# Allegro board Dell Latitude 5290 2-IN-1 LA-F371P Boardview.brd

Outline 162.9 x 178.5 mm; copper layers: TOP, IN1, GND1, IN2, GND2, VCC, IN3, GND3, IN4, BOTTOM. Coordinates in mm from the lower left corner of the outline.

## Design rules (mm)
net group ALS_I2C1_SDA: nets ALS_I2C1_SCL ALS_I2C1_SDA
net group BASE_SMBCLK: nets BASE_SMBCLK BASE_SMBDAT
net group DIFFPAIR25: nets SATA_PRX_SSDTX_N8 SATA_PRX_SSDTX_P8
net group DIFFPAIR26: nets SATA_PTX_SSDRX_N8 SATA_PTX_SSDRX_P8
net group DIFFPAIR27: nets SATA_PTX_SSDRX_N8_C SATA_PTX_SSDRX_P8_C
net group I2C1_CLK_PD1: nets I2C1_CLK_PD1 I2C1_DAT_PD1
net group I2C1_SCK_TS: nets I2C1_SCK_TS I2C1_SDA_TS
net group PD1_AUX_: nets PD1_AUX_N PD1_AUX_P
net group PD2_AUX_: nets PD2_AUX_N PD2_AUX_P
net group REM_DIODE1_P: nets REM_DIODE1_N REM_DIODE1_P
net group REM_DIODE2_P: nets REM_DIODE2_N REM_DIODE2_P
net group REM_DIODE3_P: nets REM_DIODE3_N REM_DIODE3_P
net group SD_LN0_P: nets SD_LN0_M SD_LN0_P
net group SD_LN1_P: nets SD_LN1_M SD_LN1_P
net group SD_RCLK_P: nets SD_RCLK_M SD_RCLK_P
net group SD_RCLK_P_L: nets SD_RCLK_M_L SD_RCLK_P_L
net group USB3RP1_C: nets USB3RN1_C USB3RP1_C
net group USB3TP1_C: nets USB3TN1_C USB3TP1_C
net group 10: nets CL_RST# PCH_RSMRST# PLT_RST# RTC_RST# UIM_CLK UIM_DATA UIM_DET UIM_DET# UIM_RESET WLAN_RST# WLAN_RST#_Q WWAN_RST#
net group 10_20: nets SPK_-OUT-L+ SPK_-OUT-L- SPK_-OUT-R+ SPK_-OUT-R- SPK_L+ SPK_L- SPK_R+ SPK_R-
net group 12: nets CLK1_PCIE_WLAN CLK1_PCIE_WLAN# CLK1_PCIE_WLAN#_R CLK1_PCIE_WLAN_R CLK2_PCIE_WWAN CLK2_PCIE_WWAN# CLK2_PCIE_WWAN#_R CLK2_PCIE_WWAN_R CLK_ITPXDP_N CLK_ITPXDP_N_R CLK_ITPXDP_P CLK_ITPXDP_P_R CLK_PCIE_MMI CLK_PCIE_MMI# CLK_PCIE_MMI#_R CLK_PCIE_MMI_R CLK_PCIE_SSD CLK_PCIE_SSD# CLK_PCIE_SSD#_R CLK_PCIE_SSD_R PCIE_PRX_CARDTX_N9_C PCIE_PRX_CARDTX_P9_C PCIE_PTX_CARDRX_N9_C PCIE_PTX_CARDRX_P9_C UFCAM_CSI2_CLKN0 UFCAM_CSI2_CLKN0_L UFCAM_CSI2_CLKP0 UFCAM_CSI2_CLKP0_L UFCAM_CSI2_DN0 UFCAM_CSI2_DN0_L UFCAM_CSI2_DN1 UFCAM_CSI2_DN1_L UFCAM_CSI2_DP0 UFCAM_CSI2_DP0_L UFCAM_CSI2_DP1 UFCAM_CSI2_DP1_L USB3RN1 USB3RN2 USB3RN3_CONN USB3RN4 USB3RN4_C USB3RP1 USB3RP2 USB3RP3_CONN USB3RP4 USB3RP4_C USB3TN3 USB3TN3_CONN USB3TN4 USB3TN4_C USB3TP3 USB3TP3_CONN USB3TP4 USB3TP4_C USB20_N1 USB20_N1_R USB20_N3_R USB20_N4 USB20_N4_CONN USB20_N5_CONN USB20_N10 USB20_P1 USB20_P1_R USB20_P3_R USB20_P4 USB20_P4_CONN USB20_P5_CONN USB20_P10 USBC1_BN2_L USBC1_BOT_DN2 USBC1_BOT_DP2 USBC1_BP2_L USBC1_TN1_L USBC1_TOP_DN1 USBC1_TOP_DP1 USBC1_TP1_L USBC2_BN2_L USBC2_BOT_DN2 USBC2_BOT_DP2 USBC2_BP2_L USBC2_TN1_L USBC2_TOP_DN1 USBC2_TOP_DP1 USBC2_TP1_L WFCAM_CSI2_CLKN1 WFCAM_CSI2_CLKN1_L WFCAM_CSI2_CLKP1 WFCAM_CSI2_CLKP1_L WFCAM_CSI2_DN4 WFCAM_CSI2_DN4_L WFCAM_CSI2_DN5 WFCAM_CSI2_DN5_L WFCAM_CSI2_DN6 WFCAM_CSI2_DN6_L WFCAM_CSI2_DN7 WFCAM_CSI2_DN7_L WFCAM_CSI2_DP4 WFCAM_CSI2_DP4_L WFCAM_CSI2_DP5 WFCAM_CSI2_DP5_L WFCAM_CSI2_DP6 WFCAM_CSI2_DP6_L WFCAM_CSI2_DP7 WFCAM_CSI2_DP7_L
net group 15: nets CL_CLK CL_DATA DDR_XDP_SMBCLK DDR_XDP_SMBDAT HDA_BLK HDA_BLK_L HDA_BLK_R I2C2_CLK_PD1 I2C2_DAT_PD1 ISH_I2C0_SDA JTAG_CLK MUX2_CSCL MUX2_CSDA PCH_JTAG_TCLK PCH_SPI_CLK_TPM PCI_CLK_LPC0 PCI_CLK_LPC1 SKYCAM_I2C_CLK SKYCAM_I2C_DATA SML1_SMBCLK SML1_SMBDAT SPI_CLK_VROM1 SRTCRST# SUSCLK SUSCLK_L SYS_RESET# SYS_RESET#_R UF_HCLK UF_HCLK_R UF_I2C_CLK UF_I2C_DATA UF_SENSOR_RST# UF_SENSOR_RST#_R USH_RST# USH_RST#_L VSS_GT_SENSE WF_HCLK WF_HCLK_R WF_I2C_CLK WF_I2C_DATA WF_SENSOR_RST# WF_SENSOR_RST#_R XDP_DBRESET#
net group 20: nets +V_DDR_REF_CA +V_DDR_REFA_R +V_DDR_REFB_R
net group DDR0_7.5_12_25: nets DDR_A_D16 DDR_A_D17 DDR_A_D18 DDR_A_D19 DDR_A_D20 DDR_A_D21 DDR_A_D22 DDR_A_D23 DDR_A_D32 DDR_A_D33 DDR_A_D34 DDR_A_D35 DDR_A_D36 DDR_A_D37 DDR_A_D38 DDR_A_D39 DDR_A_D48 DDR_A_D49 DDR_A_D50 DDR_A_D51 DDR_A_D52 DDR_A_D53 DDR_A_D54 DDR_A_D55 DDR_B_D0 DDR_B_D1 DDR_B_D2 DDR_B_D3 DDR_B_D4 DDR_B_D5 DDR_B_D6 DDR_B_D7 DDR_B_D16 DDR_B_D17 DDR_B_D18 DDR_B_D19 DDR_B_D20 DDR_B_D21 DDR_B_D22 DDR_B_D23 DDR_B_D32 DDR_B_D33 DDR_B_D34 DDR_B_D35 DDR_B_D36 DDR_B_D37 DDR_B_D38 DDR_B_D39 DDR_B_D48 DDR_B_D49 DDR_B_D50 DDR_B_D51 DDR_B_D52 DDR_B_D53 DDR_B_D54 DDR_B_D55 DDR_B_D56 DDR_B_D57 DDR_B_D58 DDR_B_D59 DDR_B_D60 DDR_B_D61 DDR_B_D62 DDR_B_D63
net group DDR1_7.5_12_25: nets DDR_A_D0 DDR_A_D1 DDR_A_D2 DDR_A_D3 DDR_A_D4 DDR_A_D5 DDR_A_D6 DDR_A_D7 DDR_A_D8 DDR_A_D9 DDR_A_D10 DDR_A_D11 DDR_A_D12 DDR_A_D13 DDR_A_D14 DDR_A_D15 DDR_A_D24 DDR_A_D25 DDR_A_D26 DDR_A_D27 DDR_A_D28 DDR_A_D29 DDR_A_D30 DDR_A_D31 DDR_A_D40 DDR_A_D41 DDR_A_D42 DDR_A_D43 DDR_A_D44 DDR_A_D45 DDR_A_D46 DDR_A_D47 DDR_A_D56 DDR_A_D57 DDR_A_D58 DDR_A_D59 DDR_A_D60 DDR_A_D61 DDR_A_D62 DDR_A_D63 DDR_B_D8 DDR_B_D9 DDR_B_D10 DDR_B_D11 DDR_B_D12 DDR_B_D13 DDR_B_D14 DDR_B_D15 DDR_B_D24 DDR_B_D25 DDR_B_D26 DDR_B_D27 DDR_B_D28 DDR_B_D29 DDR_B_D30 DDR_B_D31 DDR_B_D40 DDR_B_D41 DDR_B_D42 DDR_B_D43 DDR_B_D44 DDR_B_D45 DDR_B_D46 DDR_B_D47
net group DDRACMD_7.5_12: nets DDR_A_CA1_0 DDR_A_CA1_1 DDR_A_CA1_2 DDR_A_CA1_3 DDR_A_CA1_4 DDR_A_CA1_5 DDR_A_CA1_6 DDR_A_CA1_7 DDR_A_CA1_8 DDR_A_CA1_9 DDR_A_CA2_0 DDR_A_CA2_1 DDR_A_CA2_2 DDR_A_CA2_3 DDR_A_CA2_4 DDR_A_CA2_5 DDR_A_CA2_6 DDR_A_CA2_7 DDR_A_CA2_8 DDR_A_CA2_9
net group DDRBCMD_7.5_12: nets DDR_B_CA1_0 DDR_B_CA1_1 DDR_B_CA1_2 DDR_B_CA1_3 DDR_B_CA1_4 DDR_B_CA1_5 DDR_B_CA1_6 DDR_B_CA1_7 DDR_B_CA1_8 DDR_B_CA1_9 DDR_B_CA2_0 DDR_B_CA2_1 DDR_B_CA2_2 DDR_B_CA2_3 DDR_B_CA2_4 DDR_B_CA2_5 DDR_B_CA2_6 DDR_B_CA2_7 DDR_B_CA2_8 DDR_B_CA2_9
net group DDRCKE_7.5_12: nets DDR_A_CKE0 DDR_A_CKE1 DDR_A_CKE2 DDR_A_CKE3 DDR_B_CKE0 DDR_B_CKE1 DDR_B_CKE2 DDR_B_CKE3
net group DDRCLK_12_25: nets DDR_A_CLK0 DDR_A_CLK1 DDR_A_CLK#0 DDR_A_CLK#1 DDR_B_CLK0 DDR_B_CLK1 DDR_B_CLK#0 DDR_B_CLK#1
net group DDRCTL_7.5_12: nets DDR_A_CS#0 DDR_A_CS#1 DDR_A_ODT0 DDR_B_CS#0 DDR_B_CS#1 DDR_B_ODT0
net group DDRDQS_12_25: nets DDR_A_DQS0 DDR_A_DQS1 DDR_A_DQS2 DDR_A_DQS3 DDR_A_DQS4 DDR_A_DQS5 DDR_A_DQS6 DDR_A_DQS7 DDR_A_DQS#0 DDR_A_DQS#1 DDR_A_DQS#2 DDR_A_DQS#3 DDR_A_DQS#4 DDR_A_DQS#5 DDR_A_DQS#6 DDR_A_DQS#7 DDR_B_DQS0 DDR_B_DQS1 DDR_B_DQS2 DDR_B_DQS3 DDR_B_DQS4 DDR_B_DQS5 DDR_B_DQS6 DDR_B_DQS7 DDR_B_DQS#0 DDR_B_DQS#1 DDR_B_DQS#2 DDR_B_DQS#3 DDR_B_DQS#4 DDR_B_DQS#5 DDR_B_DQS#6 DDR_B_DQS#7
net group DP: nets DDI1_P2_TXN2_C DDI1_P2_TXP2 DDI1_P2_TXP2_C PD1_SBU1 PD1_SBU2 PD2_SBU1 PD2_SBU2 USBC1_SBU1 USBC2_SBU1 USBC2_SBU2 UV1_SBU1 UV1_SBU2 UV2_SBU1 UV2_SBU2
net group DP_12_15: nets DDI1_P2_TXN0 DDI1_P2_TXN0_C DDI1_P2_TXN1 DDI1_P2_TXN1_C DDI1_P2_TXN2 DDI1_P2_TXN3 DDI1_P2_TXN3_C DDI1_P2_TXP0 DDI1_P2_TXP0_C DDI1_P2_TXP1 DDI1_P2_TXP1_C DDI1_P2_TXP3 DDI1_P2_TXP3_C DDI2_P1_AUXN_C DDI2_P1_AUXP_C DDI2_P1_TXN0_C DDI2_P1_TXN1_C DDI2_P1_TXN2_C DDI2_P1_TXN3_C DDI2_P1_TXP0_C DDI2_P1_TXP1_C DDI2_P1_TXP2_C DDI2_P1_TXP3_C PCH_DDI1_AUXN PCH_DDI1_AUXN_C PCH_DDI1_AUXP PCH_DDI1_AUXP_C PCH_DDI2_AUXN PCH_DDI2_AUXP PCH_DDI2_N0 PCH_DDI2_N1 PCH_DDI2_N2 PCH_DDI2_N3 PCH_DDI2_P0 PCH_DDI2_P1 PCH_DDI2_P2 PCH_DDI2_P3 USBC1_RX1N USBC1_RX1P USBC1_RX2N USBC1_RX2P USBC1_SBU2 USBC1_TX1N USBC1_TX1N_C USBC1_TX1P USBC1_TX1P_C USBC1_TX2N USBC1_TX2N_C USBC1_TX2P USBC1_TX2P_C USBC2_RX1N USBC2_RX1P USBC2_RX2N USBC2_RX2P USBC2_TX1N USBC2_TX1N_C USBC2_TX1P USBC2_TX1P_C USBC2_TX2N USBC2_TX2N_C USBC2_TX2P USBC2_TX2P_C
net group EC: nets JTAG_TDI JTAG_TDO JTAG_TMS
net group EDP_12_15: nets EDP_AUXN EDP_AUXN_CONN EDP_AUXN_R EDP_AUXP EDP_AUXP_CONN EDP_AUXP_R EDP_TXN_P0 EDP_TXN_P0_CONN EDP_TXN_P0_R EDP_TXN_P1 EDP_TXN_P1_CONN EDP_TXN_P1_R EDP_TXP_P0 EDP_TXP_P0_CONN EDP_TXP_P0_R EDP_TXP_P1 EDP_TXP_P1_CONN EDP_TXP_P1_R
net group HDA: nets HDA_SDI0 HDA_SDI0_L HDA_SDOUT HDA_SDOUT_R HDA_SYNC HDA_SYNC_R
net group I2C: nets CLK_SMB DAT_SMB GNSS_SCL ISH_I2C0_SCL PBAT_SMBCLK PBAT_SMBDAT
net group PCH_JTAG: nets TCLK_XDP TDI_XDP TDO_XDP TMS_XDP TRST#_XDP
net group PCIE: nets PCIE_PRX_CARDTX_N9 PCIE_PRX_CARDTX_P9 PCIE_PRX_SSDTX_N7 PCIE_PRX_SSDTX_P7 PCIE_PRX_WLANTX_N5 PCIE_PRX_WLANTX_P5 PCIE_PRX_WTX_UR_N12_SW PCIE_PRX_WTX_UR_N12_SW_CONN PCIE_PRX_WTX_UR_P12_SW PCIE_PRX_WTX_UR_P12_SW_CONN PCIE_PRX_WWANTX_N11 PCIE_PRX_WWANTX_N12 PCIE_PRX_WWANTX_P11 PCIE_PRX_WWANTX_P12 PCIE_PTX_CARDRX_N9 PCIE_PTX_CARDRX_P9 PCIE_PTX_SSDRX_N7 PCIE_PTX_SSDRX_N7_C PCIE_PTX_SSDRX_P7 PCIE_PTX_SSDRX_P7_C PCIE_PTX_WLANRX_N5 PCIE_PTX_WLANRX_N5_C PCIE_PTX_WLANRX_P5 PCIE_PTX_WLANRX_P5_C PCIE_PTX_WRX_UT_N12_SW PCIE_PTX_WRX_UT_N12_SW_CONN PCIE_PTX_WRX_UT_P12_SW PCIE_PTX_WRX_UT_P12_SW_CONN PCIE_PTX_WWANRX_N11 PCIE_PTX_WWANRX_N11_C PCIE_PTX_WWANRX_N12 PCIE_PTX_WWANRX_N12_C PCIE_PTX_WWANRX_P11 PCIE_PTX_WWANRX_P11_C PCIE_PTX_WWANRX_P12 PCIE_PTX_WWANRX_P12_C
net group SD: nets SD_CLK SD_CLK_L SD_CMD SD_CMD_L SD_D2 SD_D2_L SD_D3 SD_D3_L
net group SPI: nets PCH_SPI_CLK PCH_SPI_CS0# PCH_SPI_CS1# PCH_SPI_CS2# PCH_SPI_IO2 PCH_SPI_IO3 PCH_SPI_SI PCH_SPI_SI_TPM PCH_SPI_SO PCH_SPI_SO_TPM SPI_IO2_VROM1 SPI_IO3_VROM1 SPI_SI_VROM1 SPI_SO_VROM1 TPM_PIRQ#
net group SVID: nets H_CPU_SVIDALRT# VIDALERT_N VIDSCLK VIDSCLK_R VIDSOUT VIDSOUT_R
net group USB2.0: nets USB20_N2 USB20_N3 USB20_N5 USB20_N7 USB20_N7_R USB20_N9 USB20_N9_CONN USB20_N9_PS USB20_P2 USB20_P3 USB20_P5 USB20_P7 USB20_P7_R USB20_P9 USB20_P9_CONN USB20_P9_PS
net group USB3.0: nets USB3RN3 USB3RP3 USB3TN1 USB3TN2 USB3TN2_C USB3TN3_C USB3TP1 USB3TP2 USB3TP2_C USB3TP3_C
net group XDP: nets CFG0 CFG1 CFG2 CFG3 CFG4 CFG5 CFG6 CFG7 CFG8 CFG9 CFG10 CFG11 CFG12 CFG13 CFG14 CFG15 CFG16 CFG17 CFG18 CFG19 H_VCCST_PWRGD_XDP ITP_PMODE PCH_SPI_DO2_XDP PCH_SPI_DO_XDP SIO_PWRBTN# XDP_OBS0 XDP_OBS0_R XDP_OBS1 XDP_OBS1_R
nets with their own width: min track width 0.203; nets AK52 K52 N48802004 N48802006 N51064237 N51064241
nets with their own width: min track width 0.254; nets +1.0V_PRIM_COREP +1.2V_DDR +3VS_GYRO +VCC_SA +VCCCLK1 +VCCCLK2 +VCCCLK3 +VCCCLK4 +VCCCLK5 +VCCCLK6 EN_INVPWR_R HPOL_CONN HPOR_CONN HPOUT-L HPOUT-L_L HPOUT-R HPOUT-R_L MIC2-VREFO-L MIC2-VREFO-R N28846574 N34282781 N34283012 N41312056 N46285448 VCC_GT_SENSE VCCIO_SENSE VCCSENSE VSA_SEN+ VSA_SEN- VSSIO_SENSE VSSSENSE
nets with their own width: min track width 0.305; nets CFG_RCOMP CSI2_COMP EMMC_RCOMP PCIE_RCOMPN PCIE_RCOMPP SD_RCOMP SM_RCOMP0 SM_RCOMP1 SM_RCOMP2 USBCOMP
nets with their own width: min track width 0.381; nets +3V_LDO +VREFCA
nets with their own width: min track width 0.508; nets +0.6VSP +1.0V_AMPHYPLL +1.0V_APLL +1.0V_APLLEBB +1.0V_CLK +1.0V_DTS +1.0V_MPHYAON +1.0V_PRIM_CORE +1.0V_SRAM +1.0V_VCCST +1.0V_VCCSTG +1.0V_VCCSTG_R +1.0VA_XDP +1.0VAP +1.2V_DDRP +1.2V_MEM_CPUCLK +1.2V_MUX +1.2V_UF_DVDD +1.2V_WF_DVDD +1.5VS_AUDIO +1.8V_IO_OUT +1.8V_PGPP +1.8V_UF_VDD +1.8V_WF_DOVDD +1.8VA_LDO_PD1 +1.8VA_LDO_PD2 +1.8VAP +1.8VD_LDO_PD1 +1.8VD_LDO_PD2 +1.8VS +1.8VS_AUDIO +1.8VUP +2.8V_UF_AVDD +2.8V_VCM_OUT +2.8V_WF_AVDD +3.3V_LDO_PD1 +3.3V_LDO_PD2 +3.3V_PGPP +3.3V_SPI +3.3V_TBAT_LDO +3.3V_VOUT_PD1 +3.3V_VOUT_PD2 +3V_FAN +3V_LDOP +3V_PRIM +3V_RF +3V_SKYCAM +3VALW +3VALW_PD1 +3VALW_PD2 +3VALWP +3VLP +3VS +3VS_AUDIO +3VS_ECOM +3VS_IR +3VS_IR_R +3VS_MUX +3VS_TPM +3VS_TS +5V_FAN +5VALW +5VALW_LP +5VD +5VS +AVDD1 +BAT_TABLET +BATT +BMC_LDO_PD1 +BMC_LDO_PD2 +CHG_SRC_20V +CHG_VIN_20V +DVDD +DVDDIO +INV_PWR_SRC +RTCBATT +RTCVCC +RTCVCC_EC +SD_VDD2 +SIM_PWR +VCC_CORE +VCC_CORE_G0 +VCC_CORE_G1 +VCC_GT +VCCPLL_OC +VCCPLL_OC_R +VR_CAP +VREFDQ_A +VREFDQ_B AGND CHG_ADP CPU_POPIRCOMP EDP_COMP GND GND_SIGNAL N30277718 N40373501 N41804779 PCH_POPIRCOMP PD1_CC1 PD1_CC2 PD2_CC1 PD2_CC2 TBAT_3V3 USBC1_CC1 USBC1_CC2 USBC2_CC1 USBC2_CC2
nets with their own width: min track width 0.635; nets +3VS_CAM
nets with their own width: min track width 0.762; nets +1.8VU +5VS_AUDIO +LED_AN CHG_DCIN VDD
nets with their own width: min track width 1.016; nets +1.8VA +5VALW_IR +LCDVDD +SD_VDD1 RING2_CONN SLEEVE SLEEVE_CONN
nets with their own width: min track width 1.651; nets +3VS_CR
nets with their own width: min track width 2.032; nets +3VS_WLAN +5V_DOCK +5V_USB_P1
nets with their own width: min track width 2.54; nets +3.3VDX_SSD +3VS_WWAN
nets with their own width: min track width 3.048; nets +1.0V_MPHYGT +5VALW_PD1 +5VALW_PD2 +VBUS1_20V +VBUS1_PD_20V +VBUS2_20V +VBUS2_PD_20V
nets with their own width: min track width 3.175; nets +1.0VS_VCCIO
nets with their own width: min track width 3.556; nets +1.0VA

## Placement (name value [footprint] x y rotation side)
C1  0.1U_0201_10V6K  [C_0201]  125.44 156.15 0 top
C2  0.1U_0201_10V6K  [C_0201]  125.44 168.34 0 top
C3  0.1U_0201_10V6K  [C_0201]  125.35 166.4 90 top
C4  10U_0402_6.3V6M  [C_0402]  126.11 166.36 90 top
C5  0.1U_0201_10V6K  [C_0201]  125.34 165.74 270 top
C6  2.2U_0402_6.3V6M  [C_0402]  126.07 165.25 270 top
C7  0.1U_0201_10V6K  [C_0201]  125.69 158.05 0 top
C8  0.1U_0201_10V6K  [C_0201]  119.66 161.71 180 bottom
C9  2P_0201_25V8B  [C_0201]  42.25 166.5 90 top
C10  2.2U_0402_6.3V6M  [C_0402]  125.65 158.82 0 top
C11  47P_0201_25V8J  [C_0201]  126.09 161.23 180 top
C14  0.1U_0201_10V6K  [C_0201]  125.44 155.51 0 top
C15  0.1U_0201_10V6K  [C_0201]  125.44 156.78 0 top
C16  0.1U_0201_10V6K  [C_0201]  125.44 157.42 0 top
C17  0.1U_0201_10V6K  [C_0201]  28.83 139.35 90 bottom
C18  0.1U_0201_10V6K  [C_0201]  120.56 173.93 180 top
C19  0.1U_0201_10V6K  [C_0201]  6.26 152.85 180 top
C20  0.1U_0201_10V6K  [C_0201]  6.39 139.51 180 top
C21  0.1U_0402_25V6K~D  [C_0402]  151.97 142.14 0 top
C22  1U_0402_6.3V6K~D  [C_0402]  123.62 135.04 90 top
C23  0.1U_0402_10V7K  [C_0402]  131.19 135.14 270 top
C24  2200P_0402_25V7K~D  [C_0402]  128.7 134.18 0 top
C27  1U_0402_6.3V6K  [C_0402]  35.99 99.25 0 top
C28  0.1U_0201_10V6K  [C_0201]  27.93 90.54 180 top
C29  10U_0402_6.3V6M  [C_0402]  35.99 97.98 0 top
C30  0.22U_0402_10V6K  [C_0402]  31.97 93.32 180 top
C31  0.22U_0402_10V6K  [C_0402]  31.95 94.21 180 top
C32  0.1U_0402_10V7K  [C_0402]  62.05 86.6 90 top
C37  0.1U_0402_10V7K  [C_0402]  72.59 63.31 180 top
C38  22U_0805_10V6M  [C_0805]  72.61 61.91 180 top
C39  1U_0402_6.3V6K~D  [C_0402]  71.81 54.04 0 top
C40  10U_0402_6.3V6M  [C_0402]  39.07 22.67 180 bottom
C41  10U_0402_6.3V6M  [C_0402]  39.07 23.56 180 bottom
C42  0.1U_0402_10V7K  [C_0402]  38.81 19.37 180 bottom
C43  100P_0402_50V8J  [C_0402]  142.75 136.51 90 bottom
C44  2.2U_0402_6.3V6M  [C_0402]  143.97 134.94 180 bottom
C45  47P_0201_25V8J  [C_0201]  143.8 134.18 180 bottom
C46  47P_0201_25V8J  [C_0201]  143.61 144.85 180 bottom
C47  4.3P_0402_50V8  [C_0402]  109.58 165.09 90 top
C48  0.1U_0201_10V6K  [C_0201]  110.87 165.38 90 top
C49  47P_0201_25V8J  [C_0201]  151.35 149.67 0 bottom
C50  47P_0201_25V8J  [C_0201]  150.66 149.67 180 bottom
C51  2200P_0402_25V7K~D  [C_0402]  143.81 149.42 0 bottom
C52  0.01UF_0402_25V7K  [C_0402]  152.7 148.91 0 bottom
C53  47P_0201_25V8J  [C_0201]  149.39 148.4 180 bottom
C54  1U_0201_6.3V6M  [C_0201]  149.39 147.77 180 bottom
C55  10U_0603_6.3V6M  [C_0603]  147.89 147.51 180 bottom
C56  2200P_0402_50V7K  [C_0402]  153.62 147.39 180 bottom
C57  68P_0201_25V8  [C_0201]  151.35 147.26 0 bottom
C58  68P_0201_25V8  [C_0201]  150.66 147.26 180 bottom
C59  0.1U_0402_10V7K  [C_0402]  146.48 149.86 0 bottom
C60  1U_0402_6.3V6K~D  [C_0402]  140.13 147 180 bottom
C61  4.7U_0402_6.3V6M  [C_0402]  147.78 146.37 180 bottom
C62  0.01UF_0402_25V7K  [C_0402]  152.65 145.53 90 bottom
C63  2200P_0402_50V7K  [C_0402]  151.13 146.45 270 bottom
C64  1U_0402_6.3V6K  [C_0402]  150.24 146.45 270 bottom
C65  0.1U_0201_10V6K  [C_0201]  147.74 145.61 180 bottom
C66  47P_0201_25V8J  [C_0201]  145.45 144.91 180 bottom
C67  18P_0402_50V8J  [C_0402]  154.43 144.13 90 bottom
C68  1U_0201_6.3V6M  [C_0201]  145.45 144.27 180 bottom
C69  47P_0201_25V8J  [C_0201]  145.45 143.64 180 bottom
C70  1U_0201_6.3V6M  [C_0201]  145.45 143 180 bottom
C71  18P_0402_50V8J  [C_0402]  154.43 143.27 270 bottom
C72  1U_0201_6.3V6M  [C_0201]  145.45 142.37 180 bottom
C73  33P_0402_50V8J  [C_0402]  28.96 142.25 270 bottom
C74  33P_0402_50V8J  [C_0402]  25.6 141.8 180 bottom
C75  47P_0201_25V8J  [C_0201]  145.45 141.73 180 bottom
C76  4.7U_0402_6.3V6M  [C_0402]  151.92 139.33 270 bottom
C77  47P_0201_25V8J  [C_0201]  144.87 141.04 0 bottom
C78  1U_0201_6.3V6M  [C_0201]  144.87 140.4 0 bottom
C79  0.1U_0201_10V6K  [C_0201]  153.29 142.09 270 bottom
C80  0.1U_0201_10V6K  [C_0201]  151.19 138.98 270 bottom
C81  0.1U_0402_10V7K  [C_0402]  23.75 139.71 270 bottom
C82  0.1U_0402_10V7K  [C_0402]  18.78 139.46 0 bottom
C83  33P_0402_50V8J  [C_0402]  24.69 137.23 0 bottom
C84  1000P_0402_50V7K~D  [C_0402]  21.46 138.55 90 bottom
C85  4700P_0402_25V7K  [C_0402]  20.57 138.55 90 bottom
C86  47P_0201_25V8J  [C_0201]  155.32 138.52 90 bottom
C87  1U_0201_6.3V6M  [C_0201]  154.69 138.52 90 bottom
C88  4.7U_0402_6.3V6M  [C_0402]  149.1 138.83 270 bottom
C89  0.1U_0402_10V7K  [C_0402]  36.96 146.74 90 bottom
C90  1U_0402_6.3V6K~D  [C_0402]  36.31 136.15 0 bottom
C91  220P_0402_50V8K  [C_0402]  30.94 136.84 180 bottom
C92  2200P_0402_25V7K~D  [C_0402]  30.94 135.96 180 bottom
C93  1U_0402_6.3V6K~D  [C_0402]  23.37 134.99 90 bottom
C94  1U_0402_6.3V6K~D  [C_0402]  18.92 134.74 90 bottom
C95  0.1U_0402_10V7K  [C_0402]  28.7 134.74 90 bottom
C96  1U_0402_6.3V6K~D  [C_0402]  36.31 134.37 0 bottom
C97  100U_A1_6.3VM_R70M  [C_NEC]  35.76 126.18 90 bottom
C98  100U_A1_6.3VM_R70M  [C_NEC]  33.78 126.18 90 bottom
C99  22U_0603_6.3V6M  [C_0603]  16.7 125.29 90 bottom
C100  47P_0402_50V8J  [C_0402]  16.56 124.33 0 bottom
C101  0.1U_0201_10V6K  [C_0201]  16.98 123.57 0 bottom
C102  33P_0201_50V8J  [C_0201]  16.38 123.38 270 bottom
C103  22U_0603_6.3V6M  [C_0603]  32.19 125.35 90 bottom
C104  47P_0402_50V8J  [C_0402]  32.83 123.52 270 bottom
C105  0.1U_0201_10V6K  [C_0201]  33.31 121.71 270 bottom
C106  33P_0201_50V8J  [C_0201]  33.88 121.71 270 bottom
C107  0.1U_0402_10V7K  [C_0402]  18.41 125.36 270 bottom
C108  0.1U_0201_10V6K  [C_0201]  30.46 124.07 0 bottom
C110  0.1U_0201_10V6K  [C_0201]  22.54 104.81 270 bottom
C111  0.1U_0201_10V6K  [C_0201]  23.14 104.81 270 bottom
C112  1U_0402_6.3V6K  [C_0402]  153.22 102.37 315 bottom
C113  47U_0805_6.3V6M  [C_0805]  19.53 96.55 270 bottom
C114  47U_0805_6.3V6M  [C_0805]  19.49 98.34 90 bottom
C115  0.1U_0201_10V6K  [C_0201]  18.22 96.5 270 bottom
C116  0.1U_0402_10V7K  [C_0402]  24.23 86.77 180 bottom
C117  1U_0402_6.3V6K~D  [C_0402]  17.58 86.96 180 bottom
C118  2200P_0402_25V7K~D  [C_0402]  23.32 85.88 0 bottom
C119  2200P_0402_25V7K~D  [C_0402]  23.32 84.99 0 bottom
C120  0.1U_0402_10V7K  [C_0402]  24.23 83.08 90 bottom
C121  1U_0402_6.3V6K~D  [C_0402]  17.58 84.9 180 bottom
C124  1U_0402_6.3V6K~D  [C_0402]  52.4 89.73 180 bottom
C125  0.1U_0201_10V6K  [C_0201]  43.26 92.34 0 bottom
C126  0.1U_0402_10V7K  [C_0402]  46.1 88.71 270 bottom
C127  1000P_0402_50V7K~D  [C_0402]  48.72 87.82 180 bottom
C128  0.1U_0201_10V6K  [C_0201]  38.19 89.52 180 bottom
C129  2200P_0402_25V7K~D  [C_0402]  48.72 86.93 180 bottom
C130  10U_0603_6.3V6M  [C_0603]  38.87 88.6 180 bottom
C131  0.1U_0402_10V7K  [C_0402]  46.1 86.02 90 bottom
C132  1U_0402_6.3V6K~D  [C_0402]  52.4 85.16 180 bottom
C133  2.2P_0402_50V8C~D  [C_0402]  45.21 80.02 270 bottom
C134  2.2P_0402_50V8C~D  [C_0402]  41.91 80.02 270 bottom
C135  33P_0402_50V8J  [C_0402]  41.02 79.11 90 bottom
C136  2.2P_0402_50V8C~D  [C_0402]  41.91 76.47 270 bottom
C137  47P_0402_50V8J~D  [C_0402]  41.02 76.47 270 bottom
C138  2.2P_0402_50V8C~D  [C_0402]  41.91 78.25 270 bottom
C139  33P_0402_50V8J  [C_0402]  63.88 75.33 270 bottom
C140  47P_0402_50V8J  [C_0402]  62.99 75.33 270 bottom
C141  0.1U_0402_10V7K  [C_0402]  46.86 74.66 90 bottom
C142  4.7U_0402_6.3V6M  [C_0402]  45.72 75.69 270 bottom
C143  4.7U_0402_6.3V6M  [C_0402]  44.45 75.69 270 bottom
C144  0.1U_0402_10V7K  [C_0402]  42.99 73.65 90 bottom
C145  4.7U_0402_6.3V6M  [C_0402]  42.1 73.65 90 bottom
C146  10U_0402_6.3V6M  [C_0402]  20.36 60.9 0 bottom
C147  10U_0402_6.3V6M  [C_0402]  21.82 57.04 0 bottom
C148  10U_0402_6.3V6M  [C_0402]  20.36 60.01 0 bottom
C149  15P_0402_50V8J  [C_0402]  21.63 58.19 0 bottom
C150  0.1U_0201_10V6K  [C_0201]  20.64 59.22 0 bottom
C151  0.1U_0201_10V6K  [C_0201]  20.19 66.65 270 bottom
C152  15P_0402_50V8J  [C_0402]  35.97 58.42 180 bottom
C153  10U_0402_6.3V6M  [C_0402]  36.83 57.43 270 bottom
C154  10U_0402_6.3V6M  [C_0402]  35.94 57.43 270 bottom
C155  10U_0402_6.3V6M  [C_0402]  35.05 57.43 270 bottom
C156  0.1U_0201_10V6K  [C_0201]  37.59 57.52 270 bottom
C159  0.01U_0201_25V6K  [C_0201]  9.68 41.55 180 bottom
C160  0.01U_0201_25V6K  [C_0201]  9.68 40.98 180 bottom
C161  0.01U_0201_25V6K  [C_0201]  9.68 40.41 180 bottom
C163  0.01U_0201_25V6K  [C_0201]  9.68 39.84 180 bottom
C165  0.1U_0402_25V6  [C_0402]  9.02 39.7 270 top
C167  0.1U_0402_10V7K  [C_0402]  82.04 35.7 0 bottom
C169  0.1U_0402_10V7K  [C_0402]  82.96 37.48 180 bottom
C172  33P_0402_50V8J  [C_0402]  82.96 36.59 180 bottom
C174  10U_0402_6.3V6M  [C_0402]  82.96 33.92 180 bottom
C175  0.1U_0201_10V6K  [C_0201]  80.84 35.02 90 bottom
C176  0.1U_0201_10V6K  [C_0201]  80.2 35.02 90 bottom
C177  0.1U_0201_10V6K  [C_0201]  78.99 35.02 90 bottom
C178  0.1U_0201_10V6K  [C_0201]  78.36 35.02 90 bottom
C179  0.1U_0201_10V6K  [C_0201]  77.15 35.02 90 bottom
C180  0.1U_0201_10V6K  [C_0201]  76.52 35.02 90 bottom
C182  10U_0402_6.3V6M  [C_0402]  82.96 34.81 180 bottom
C188  0.1U_0402_50V7K  [C_0402]  82.52 31.14 90 bottom
C189  0.1U_0402_50V7K  [C_0402]  81.64 31.14 90 bottom
C190  0.1U_0402_50V7K  [C_0402]  80.75 31.14 90 bottom
C191  0.1U_0201_10V6K  [C_0201]  82.99 28.36 270 bottom
C192  0.01U_0201_25V6K  [C_0201]  9.56 26.93 180 bottom
C193  0.1U_0402_10V7K  [C_0402]  81.34 27.55 90 bottom
C194  0.1U_0402_10V7K  [C_0402]  75.01 27.88 180 bottom
C195  0.01U_0201_25V6K  [C_0201]  9.56 26.29 180 bottom
C196  15P_0402_50V8J  [C_0402]  82.23 28.46 270 bottom
C197  0.01U_0201_25V6K  [C_0201]  9.56 25.66 180 bottom
C198  0.1U_0402_10V7K  [C_0402]  70.74 26.81 270 bottom
C199  0.01U_0201_25V6K  [C_0201]  9.56 27.56 180 bottom
C200  2200P_0402_25V7K~D  [C_0402]  73.91 25.39 90 bottom
C201  2200P_0402_25V7K~D  [C_0402]  73.03 25.39 90 bottom
C202  0.1U_0402_25V6  [C_0402]  9.02 24.72 270 top
C203  1U_0402_6.3V6K~D  [C_0402]  74.8 20.08 270 bottom
C205  1U_0402_6.3V6K~D  [C_0402]  23.61 128.72 0 bottom
C206  220P_0402_50V8K  [C_0402]  23.61 126.94 0 bottom
C207  4.7U_0402_6.3V6M  [C_0402]  16.51 128.67 270 bottom
C208  10U_0402_6.3V6M  [C_0402]  127 166.6 270 top
C209  10U_0402_6.3V6M  [C_0402]  127 167.43 90 top
C210  10U_0402_6.3V6M  [C_0402]  125.48 162.07 270 bottom
C211  10U_0402_6.3V6M  [C_0402]  124.59 162.07 270 bottom
C212  10U_0402_6.3V6M  [C_0402]  126.36 162.07 270 bottom
C215  0.1U_0201_10V6K  [C_0201]  24.13 108.8 90 top
C217  0.1U_0201_10V6K  [C_0201]  23.5 108.8 90 top
C219  10P_0201_25V8  [C_0201]  134.39 94.43 0 top
C220  10P_0201_25V8  [C_0201]  128.23 93.93 0 top
C221  10P_0201_25V8  [C_0201]  127.61 93.93 180 top
C222  10P_0201_25V8  [C_0201]  72.71 56.16 90 top
C223  10P_0201_25V8  [C_0201]  72.71 55.54 270 top
C224  0.1U_0201_10V6K  [C_0201]  42.06 97.58 180 bottom
C225  10U_0402_6.3V6M  [C_0402]  41.91 98.49 180 bottom
C226  0.1U_0201_10V6K  [C_0201]  40.17 89.14 270 bottom
C227  10U_0402_6.3V6M  [C_0402]  28.64 90.7 0 top
C228  10U_0402_6.3V6M  [C_0402]  30.85 90.7 90 top
C229  10U_0603_6.3V6M  [C_0603]  36.96 97.35 180 bottom
C230  0.1U_0201_10V6K  [C_0201]  35.43 95.95 180 bottom
C231  0.1U_0402_25V6K~D  [C_0402]  80.61 80.9 0 top
C232  0.1U_0402_25V6K~D  [C_0402]  79.35 73.76 270 top
C233  10U_0603_25V6M  [C_0603]  79.34 74.8 90 top
C236  0.1U_0201_10V6K  [C_0201]  31.95 99.51 180 bottom
C500  0.1U_0402_10V7K  [C_0402]  122.97 160.34 90 bottom
C501  0.1U_0402_10V7K  [C_0402]  122.97 159.39 270 bottom
C502  0.1U_0402_10V7K  [C_0402]  135.95 149.49 90 bottom
C503  0.1U_0402_10V7K  [C_0402]  137.29 136.15 0 bottom
C504  0.1U_0402_10V7K  [C_0402]  142.04 134.77 90 bottom
C1034  68P_0402_50V8J  [C_0402]  13.47 103.57 180 top
C1035  10U_0402_6.3V6M  [C_0402]  13.47 102.68 180 top
C1036  0.1U_0201_10V6K  [C_0201]  13.5 101.92 180 top
C1037  0.1U_0201_10V6K  [C_0201]  13.5 101.28 180 top
C1038  1U_1206_50V7  [C_1206]  72.83 50.61 180 top
C1039  2P_0201_25V8B  [C_0201]  44.15 166.5 90 top
C1040  1U_0402_6.3V6K~D  [C_0402]  31.62 93.79 270 bottom
C1120  100P_0402_50V8J  [C_0402]  153.67 136.81 90 top
C1121  1U_0201_6.3V6M  [C_0201]  149.42 91.92 270 bottom
C1122  1U_0201_6.3V6M  [C_0201]  149.42 89.51 270 bottom
C1123  1U_0201_6.3V6M  [C_0201]  142.18 89.51 270 bottom
C1124  1U_0201_6.3V6M  [C_0201]  142.18 91.92 270 bottom
C1125  1U_0402_25V6K  [C_0402]  124.08 88.83 90 bottom
C1126  1U_0201_6.3V6M  [C_0201]  149.42 90.13 90 bottom
C1127  1U_0201_6.3V6M  [C_0201]  149.44 92.55 90 bottom
C1128  1U_0201_6.3V6M  [C_0201]  142.18 92.55 90 bottom
C1129  1U_0201_6.3V6M  [C_0201]  142.18 90.13 90 bottom
C1130  1U_0402_25V6K  [C_0402]  124.08 92.06 90 bottom
C1131  0.1U_0402_25V6K~D  [C_0402]  29.08 99.23 90 bottom
C1132  22P_0402_50V8J  [C_0402]  26.53 95.92 270 bottom
C1133  0.1U_0201_10V6K  [C_0201]  33.66 101.47 270 bottom
C1134  0.1U_0201_10V6K  [C_0201]  52.4 102.85 180 bottom
C1136  1U_0402_6.3V6K~D  [C_0402]  70.23 84.93 0 bottom
C1137  2200P_0402_25V7K~D  [C_0402]  64.96 84.05 180 bottom
C1138  0.1U_0402_10V7K  [C_0402]  62.64 85.18 180 bottom
CA1  0.1U_0201_10V6K  [C_0201]  13.46 173.8 90 top
CA2  0.1U_0201_10V6K  [C_0201]  111.66 169.71 90 top
CA3  100P_0402_50V8J~D  [C_0402]  94.61 139.02 270 top
CA4  100P_0402_50V8J~D  [C_0402]  97.84 134.69 0 top
CA5  0.1U_0201_10V6K  [C_0201]  5.42 131.32 0 top
CA6  0.1U_0201_10V6K  [C_0201]  125.34 163.97 90 top
CA7  1000P_0201_50V7K  [C_0201]  14.52 161.36 180 bottom
CA8  1000P_0201_50V7K  [C_0201]  12.53 161.36 0 bottom
CA9  330P_0402_50V8J  [C_0402]  20.14 152.34 180 bottom
CA10  10U_0402_6.3V6M  [C_0402]  9.59 157.93 180 bottom
CA11  330P_0402_50V8J  [C_0402]  21.92 152.34 180 bottom
CA12  10U_0402_6.3V6M  [C_0402]  10.6 157.93 0 bottom
CA13  100P_0201_25V7K  [C_0201]  25.91 152.31 270 bottom
CA14  0.1U_0201_10V6K  [C_0201]  25.27 152.31 270 bottom
CA15  10U_0603_6.3V6M  [C_0603]  24.45 152.85 180 bottom
CA16  0.1U_0201_10V6K  [C_0201]  29.38 151.2 180 bottom
CA17  2.2U_0402_6.3V6M  [C_0402]  29.54 151.96 180 bottom
CA18  1U_0603_10V6K  [C_0603]  20 150.81 180 bottom
CA19  10U_0603_6.3V6M  [C_0603]  35.05 149.1 90 bottom
CA20  10U_0603_6.3V6M  [C_0603]  32.45 151.32 0 bottom
CA21  1U_0603_10V6K  [C_0603]  18.61 149.42 0 bottom
CA22  10U_0603_6.3V6M  [C_0603]  32.45 150.05 0 bottom
CA23  0.1U_0201_10V6K  [C_0201]  31.62 149.76 90 bottom
CA24  0.1U_0201_10V6K  [C_0201]  19.98 148.27 180 bottom
CA25  10U_0603_6.3V6M  [C_0603]  31.11 148.21 270 bottom
CA26  0.1U_0201_10V6K  [C_0201]  30.1 147.87 270 bottom
CA27  0.1U_0201_10V6K  [C_0201]  19.94 146.97 90 bottom
CA28  10U_0402_6.3V6M  [C_0402]  19.19 147.07 180 bottom
CA29  10U_0603_6.3V6M  [C_0603]  19.88 145.99 180 bottom
CA30  0.1U_0201_10V6K  [C_0201]  31.27 145.31 90 bottom
CA31  10U_0603_10V6M  [C_0603]  32.19 145.86 270 bottom
CA32  10U_0603_6.3V6M  [C_0603]  19.88 143.7 180 bottom
CA33  0.1U_0201_10V6K  [C_0201]  26.38 142.56 0 bottom
CA34  22P_0201_25V8  [C_0201]  25.57 142.56 180 bottom
CA35  22P_0201_25V8  [C_0201]  28.19 142.34 270 bottom
CA36  0.1U_0201_10V6K  [C_0201]  21.21 142.34 270 bottom
CA37  22P_0402_50V8G  [C_0402]  22.86 142.38 270 bottom
CA38  2.2U_0402_6.3V6M  [C_0402]  20.45 142.38 270 bottom
CA39  2.2U_0402_6.3V6M  [C_0402]  26.47 141.8 0 bottom
CA40  0.1U_0402_10V7K  [C_0402]  31.32 141.7 180 bottom
CA41  22P_0201_25V8  [C_0201]  24.85 139.77 0 bottom
CA42  1000P_0402_50V7K~D  [C_0402]  69.04 18.35 180 bottom
CA43  1000P_0402_50V7K~D  [C_0402]  68.2 15.24 180 bottom
CA44  1000P_0402_50V7K~D  [C_0402]  68.07 13.46 90 bottom
CA45  1000P_0402_50V7K~D  [C_0402]  68.07 12.59 270 bottom
CA46  0.22U_0402_16V7K  [C_0402]  28.45 153.09 90 bottom
CA47  0.22U_0402_16V7K  [C_0402]  26.92 153.94 270 bottom
CA48  0.22U_0402_16V7K  [C_0402]  25.4 153.02 90 bottom
CA49  1000P_0201_50V7K  [C_0201]  9.07 160.72 0 bottom
CA50  1000P_0201_50V7K  [C_0201]  11.2 160.72 180 bottom
CC1  15P_0201_50V8J  [C_0201]  73.15 138.32 180 top
CC2  15P_0201_50V8J  [C_0201]  73.85 138.28 0 top
CC3  1U_0402_6.3V6K  [C_0402]  64.06 137.1 0 top
CC4  1U_0402_6.3V6K  [C_0402]  67.01 137.1 180 top
CC5  0.1U_0201_10V6K  [C_0201]  62.32 136.97 0 top
CC7  33P_0201_50V8J  [C_0201]  97.71 127.19 0 top
CC8  33P_0201_50V8J  [C_0201]  97.71 126.3 0 top
CC11  33P_0201_50V8J  [C_0201]  97.71 125.16 0 top
CC13  33P_0201_50V8J  [C_0201]  97.71 124.27 0 top
CC14  1U_0402_6.3V6K  [C_0402]  47.19 119.45 180 top
CC15  0.1U_0402_10V7K  [C_0402]  100.47 120.33 180 top
CC16  0.01U_0402_16V7K  [C_0402]  65.04 108.84 180 top
CC17  22P_0402_50V8J  [C_0402]  68.71 108.85 270 top
CC18  10U_0402_6.3V6M  [C_0402]  72.85 108.4 180 top
CC19  10U_0402_6.3V6M  [C_0402]  75.23 108.4 0 top
CC20  10U_0402_6.3V6M  [C_0402]  79.45 108.4 180 top
CC22  1U_0402_6.3V6K  [C_0402]  64.14 105.17 270 top
CC23  6.8P_0402_50V8J  [C_0402]  58.72 103.7 0 top
CC24  6.8P_0402_50V8J  [C_0402]  61.42 103.7 180 top
CC25  1U_0402_6.3V6K  [C_0402]  65.15 100.32 90 top
CC26  0.1U_0402_25V6  [C_0402]  150.11 134.99 90 bottom
CC27  22U_0603_6.3V6M  [C_0603]  57.49 134.81 180 bottom
CC28  1U_0402_6.3V6K  [C_0402]  61.09 133.34 90 bottom
CC29  47U_0805_6.3V6M  [C_0805]  52.83 134.6 90 bottom
CC30  22U_0603_6.3V6M  [C_0603]  57.49 133.54 180 bottom
CC32  1U_0402_6.3V6K  [C_0402]  63.17 130.62 0 bottom
CC33  0.1U_0402_10V7K  [C_0402]  158.04 130.24 0 bottom
CC34  1U_0402_6.3V6K  [C_0402]  61.8 129.86 180 bottom
CC35  1U_0402_6.3V6K  [C_0402]  66.31 129.73 180 bottom
CC36  0.1U_0402_25V6  [C_0402]  150.19 129.61 180 bottom
CC37  0.1U_0402_10V7K  [C_0402]  158.04 129.35 0 bottom
CC38  1U_0402_6.3V6K  [C_0402]  63.63 128 90 bottom
CC39  1U_0402_6.3V6K  [C_0402]  62.74 128 90 bottom
CC40  0.1U_0201_10V6K  [C_0201]  65.66 127.84 90 bottom
CC41  0.1U_0201_10V6K  [C_0201]  65.02 128.42 270 bottom
CC42  0.1U_0201_10V6K  [C_0201]  64.39 128.42 270 bottom
CC43  47U_0805_6.3V6M  [C_0805]  56.91 125.76 270 bottom
CC44  1U_0402_6.3V6K  [C_0402]  65.71 126.43 0 bottom
CC45  1U_0402_6.3V6K  [C_0402]  61.72 125.4 90 bottom
CC46  4.7P_0402_50V8C  [C_0402]  65.07 125.48 0 bottom
CC47  47U_0805_6.3V6M  [C_0805]  51.9 125.29 180 bottom
CC48  1U_0402_6.3V6K  [C_0402]  51.77 123.89 180 bottom
CC49  2P_0201_25V8B  [C_0201]  60.33 124.06 270 bottom
CC50  1U_0402_6.3V6K  [C_0402]  62.36 122.92 90 bottom
CC51  1U_0402_6.3V6K  [C_0402]  64.15 123.13 180 bottom
CC52  47U_0805_6.3V6M  [C_0805]  66.17 123.24 270 bottom
CC53  2P_0201_25V8B  [C_0201]  58.42 122.53 270 bottom
CC54  1U_0402_6.3V6K  [C_0402]  64.82 121.4 180 bottom
CC55  22U_0603_6.3V6M  [C_0603]  51.75 121.48 180 bottom
CC56  1U_0402_6.3V6K  [C_0402]  65.46 120.52 0 bottom
CC57  0.1U_0402_10V7K  [C_0402]  64.59 120.52 180 bottom
CC58  1U_0402_6.3V6K  [C_0402]  61.77 120.46 0 bottom
CC59  22U_0603_6.3V6M  [C_0603]  51.75 120.21 180 bottom
CC60  1U_0402_6.3V6K  [C_0402]  69.28 119.24 90 bottom
CC61  1U_0402_6.3V6K  [C_0402]  71.95 119.24 90 bottom
CC62  10U_0402_6.3V6M  [C_0402]  71.06 119.24 90 bottom
CC63  1U_0402_6.3V6K  [C_0402]  70.17 119.24 90 bottom
CC64  2P_0201_25V8B  [C_0201]  64.92 119.79 270 bottom
CC65  1U_0201_6.3V6M  [C_0201]  76.77 119.39 270 bottom
CC66  1U_0201_6.3V6M  [C_0201]  77.34 119.39 270 bottom
CC67  10U_0402_6.3V6M  [C_0402]  70.98 118.38 270 bottom
CC68  1U_0201_6.3V6M  [C_0201]  66.42 118.64 90 bottom
CC69  1U_0402_6.3V6K  [C_0402]  78.11 119.84 270 bottom
CC70  0.1U_0402_10V7K  [C_0402]  63.5 118.12 270 bottom
CC71  1U_0201_6.3V6M  [C_0201]  70.22 118.28 270 bottom
CC72  1U_0201_6.3V6M  [C_0201]  69.65 118.28 270 bottom
CC73  47U_0805_6.3V6M  [C_0805]  50.28 117.41 0 bottom
CC74  1U_0201_6.3V6M  [C_0201]  69.91 114.47 270 bottom
CC75  1U_0201_6.3V6M  [C_0201]  66.48 114.96 90 bottom
CC76  1U_0201_6.3V6M  [C_0201]  77.94 118.24 0 bottom
CC77  1U_0201_6.3V6M  [C_0201]  73.57 115 180 bottom
CC78  12P_0402_50V8J  [C_0402]  25.97 102.92 90 bottom
CC79  1U_0402_6.3V6K  [C_0402]  61.34 112.51 90 bottom
CC80  1U_0201_6.3V6M  [C_0201]  66.8 112.42 90 bottom
CC81  0.1U_0402_10V7K  [C_0402]  59.72 112.21 90 bottom
CC82  10U_0402_6.3V6M  [C_0402]  72.85 109.41 180 top
CC83  10U_0402_6.3V6M  [C_0402]  78.03 117.03 0 bottom
CC84  10U_0402_6.3V6M  [C_0402]  79.45 109.41 180 top
CC85  10U_0402_6.3V6M  [C_0402]  75.23 109.41 0 top
CC86  22U_0603_6.3V6M  [C_0603]  79.5 111.38 270 bottom
CC87  22U_0603_6.3V6M  [C_0603]  76.33 111.38 270 bottom
CC88  22U_0603_6.3V6M  [C_0603]  74.04 110.36 90 bottom
CC90  0.1U_0402_25V6  [C_0402]  56.9 100.52 0 bottom
CC91  33P_0402_50V8J  [C_0402]  50.47 100.61 90 bottom
CC92  2P_0201_25V8B  [C_0201]  58.29 123.79 90 bottom
CC93  2P_0201_25V8B  [C_0201]  65.79 107.1 270 top
CC94  2P_0201_25V8B  [C_0201]  67.65 107.25 0 top
CC95  0.1U_0402_25V6  [C_0402]  158.04 132.02 0 bottom
CC96  27P_0201_25V8  [C_0201]  49.59 131.34 0 top
CC97  27P_0201_25V8  [C_0201]  51.36 131.34 180 top
CC98  33P_0402_50V8J  [C_0402]  45.01 125.29 0 top
CC99  33P_0402_50V8J  [C_0402]  44.99 126.23 0 top
CD1  10U_0603_6.3V6M~D  [C_0603]  72.54 104.42 180 top
CD2  10U_0603_6.3V6M~D  [C_0603]  102.62 105.08 0 top
CD3  10U_0603_6.3V6M~D  [C_0603]  72.54 103.15 180 top
CD4  0.1U_0402_16V7K~D  [C_0402]  74.38 104.96 90 top
CD5  1U_0402_6.3V6K~D  [C_0402]  75.39 104.96 90 top
CD6  0.1U_0402_16V7K~D  [C_0402]  76.41 104.96 90 top
CD7  1U_0402_6.3V6K~D  [C_0402]  78.73 104.9 90 top
CD8  1U_0402_6.3V6K~D  [C_0402]  81.28 106.8 90 top
CD9  1U_0402_6.3V6K~D  [C_0402]  104.97 104.25 90 top
CD10  1U_0402_6.3V6K~D  [C_0402]  93.27 106.16 90 top
CD11  1U_0402_6.3V6K~D  [C_0402]  80.39 106.8 90 top
CD12  10U_0603_6.3V6M~D  [C_0603]  101.79 90.08 180 bottom
CD13  1U_0402_6.3V6K~D  [C_0402]  82.17 106.8 90 top
CD14  1U_0402_6.3V6K~D  [C_0402]  105.88 104.26 90 top
CD15  1U_0402_6.3V6K~D  [C_0402]  73.49 104.96 90 top
CD16  0.1U_0402_16V7K~D  [C_0402]  106.39 101.91 270 top
CD17  10U_0603_6.3V6M~D  [C_0603]  72.42 100.58 90 top
CD18  1U_0402_6.3V6K~D  [C_0402]  101.81 90.22 270 top
CD19  0.047U_0402_10V7K~D  [C_0402]  72.58 98.76 180 top
CD20  0.022U_0402_16V7K~D  [C_0402]  70.45 98.15 180 bottom
CD21  0.047U_0402_10V7K~D  [C_0402]  102.67 96.71 0 top
CD22  0.047U_0402_10V7K~D  [C_0402]  86.81 96.73 0 top
CD23  1U_0402_6.3V6K~D  [C_0402]  102.79 95.57 0 top
CD24  1U_0402_6.3V6K~D  [C_0402]  102.79 94.68 0 top
CD25  1U_0402_6.3V6K~D  [C_0402]  94.16 106.16 90 top
CD26  0.1U_0402_16V7K~D  [C_0402]  72.5 95.12 180 top
CD27  0.1U_0402_16V7K~D  [C_0402]  102.79 93.79 0 top
CD28  0.1U_0402_16V7K~D  [C_0402]  72.5 94.22 180 top
CD29  1U_0402_6.3V6K~D  [C_0402]  86.81 95.77 0 top
CD30  1U_0402_6.3V6K~D  [C_0402]  72.5 93.33 180 top
CD31  10U_0603_6.3V6M~D  [C_0603]  102.81 92.65 0 top
CD32  10U_0603_6.3V6M~D  [C_0603]  102.81 91.38 0 top
CD33  1U_0402_6.3V6K~D  [C_0402]  71.68 96.08 90 top
CD34  1U_0402_6.3V6K~D  [C_0402]  78.75 90.24 180 top
CD35  1U_0402_6.3V6K~D  [C_0402]  79.59 90.22 0 top
CD36  1U_0402_6.3V6K~D  [C_0402]  96.59 90.25 180 top
CD37  1U_0402_6.3V6K~D  [C_0402]  98.37 90.25 180 top
CD38  1U_0402_6.3V6K~D  [C_0402]  102.79 90.2 0 top
CD39  1U_0402_6.3V6K~D  [C_0402]  105.46 101.91 270 top
CD40  10U_0603_6.3V6M~D  [C_0603]  92.45 90.1 180 top
CD41  10U_0603_6.3V6M~D  [C_0603]  93.39 90.1 0 top
CD42  0.22U_0402_10V6K  [C_0402]  54.29 85.55 270 top
CD43  0.22U_0402_10V6K  [C_0402]  55.18 85.55 270 top
CD44  0.22U_0402_10V6K  [C_0402]  57.35 85.74 270 top
CD45  0.22U_0402_10V6K  [C_0402]  58.24 85.74 270 top
CD46  0.022U_0402_16V7K~D  [C_0402]  91.2 108.27 180 bottom
CD47  0.047U_0402_10V7K~D  [C_0402]  90.25 107.38 180 bottom
CD48  10U_0603_6.3V6M~D  [C_0603]  80.52 106.36 180 bottom
CD49  10U_0603_6.3V6M~D  [C_0603]  80.52 105.09 180 bottom
CD50  10U_0603_6.3V6M~D  [C_0603]  97.43 105.01 0 top
CD51  1U_0402_6.3V6K~D  [C_0402]  77.62 105.02 90 bottom
CD52  1U_0402_6.3V6K~D  [C_0402]  76.52 105.02 90 bottom
CD53  1U_0402_6.3V6K~D  [C_0402]  75.63 105.02 90 bottom
CD54  1U_0402_6.3V6K~D  [C_0402]  94.44 104.84 180 top
CD55  1U_0402_6.3V6K~D  [C_0402]  77.84 104.9 90 top
CD56  1U_0402_6.3V6K~D  [C_0402]  102.79 104.4 0 bottom
CD57  0.1U_0402_16V7K~D  [C_0402]  100.32 105.73 0 bottom
CD58  1U_0402_6.3V6K~D  [C_0402]  100.32 104.78 0 bottom
CD59  10U_0603_6.3V6M~D  [C_0603]  102.81 90.74 0 bottom
CD60  1U_0402_6.3V6K~D  [C_0402]  102.79 103.44 0 bottom
CD61  1U_0402_6.3V6K~D  [C_0402]  102.79 102.43 0 bottom
CD62  10U_0603_6.3V6M~D  [C_0603]  71.2 100.58 90 top
CD63  1U_0402_6.3V6K~D  [C_0402]  102.79 101.41 0 bottom
CD64  10U_0603_6.3V6M~D  [C_0603]  72.25 101.02 180 bottom
CD65  1U_0402_6.3V6K~D  [C_0402]  102.79 100.4 0 bottom
CD66  1U_0402_6.3V6K~D  [C_0402]  72.25 99.96 180 bottom
CD67  0.022U_0402_16V7K~D  [C_0402]  104.52 100.34 270 top
CD68  1U_0402_6.3V6K~D  [C_0402]  72.25 99.07 180 bottom
CD69  0.047U_0402_10V7K~D  [C_0402]  86.86 98.36 0 bottom
CD70  0.047U_0402_10V7K~D  [C_0402]  72.24 97.22 180 bottom
CD71  0.047U_0402_10V7K~D  [C_0402]  102.67 97.6 0 top
CD72  0.047U_0402_10V7K~D  [C_0402]  86.86 97.47 0 bottom
CD73  10U_0603_6.3V6M~D  [C_0603]  72.77 96.13 180 bottom
CD74  0.1U_0402_16V7K~D  [C_0402]  102.79 99.38 0 bottom
CD75  1U_0402_6.3V6K~D  [C_0402]  72.84 95.04 180 bottom
CD76  1U_0402_6.3V6K~D  [C_0402]  72.84 94.15 180 bottom
CD77  1U_0402_6.3V6K~D  [C_0402]  102.79 98.36 0 bottom
CD78  1U_0402_6.3V6K~D  [C_0402]  72.84 93.26 180 bottom
CD79  1U_0402_6.3V6K~D  [C_0402]  103.11 93.16 0 bottom
CD80  10U_0603_6.3V6M~D  [C_0603]  102.81 92.01 0 bottom
CD81  10U_0603_6.3V6M~D  [C_0603]  72.77 91.89 180 bottom
CD82  1U_0402_6.3V6K~D  [C_0402]  72.79 90.74 180 bottom
CD83  1U_0402_6.3V6K~D  [C_0402]  97.84 90.24 0 bottom
CD84  1U_0402_6.3V6K~D  [C_0402]  78.86 90.36 0 bottom
CD85  1U_0402_6.3V6K~D  [C_0402]  75.35 90.29 180 bottom
CD100  1U_0201_6.3V6M  [C_0201]  87.48 92.01 180 top
CD101  1U_0201_6.3V6M  [C_0201]  85.43 106.07 90 bottom
CD102  1U_0201_6.3V6M  [C_0201]  88.23 106.07 90 bottom
CD103  1U_0201_6.3V6M  [C_0201]  90.68 105.98 90 top
CD104  22U_0402_6.3V6M  [C_0402]  84.47 106.41 90 top
CD105  1U_0201_6.3V6M  [C_0201]  87.94 92.07 0 bottom
CD106  1U_0201_6.3V6M  [C_0201]  88.15 91.48 0 top
CD107  1U_0201_6.3V6M  [C_0201]  87.35 91.66 180 bottom
CD108  1U_0201_6.3V6M  [C_0201]  81.76 106.08 180 top
CD109  22U_0402_6.3V6M  [C_0402]  83.58 106.41 90 top
CE1  100P_0402_50V8J  [C_0402]  5.08 161.95 0 top
CE2  100P_0402_50V8J  [C_0402]  66.27 108.38 180 bottom
CE3  100P_0402_50V8J  [C_0402]  45.29 87.44 180 top
CE4  100P_0402_50V8J  [C_0402]  20.32 17.85 90 top
CE8  0.1U_0201_10V6K  [C_0201]  33.02 114.14 0 bottom
CE9  4700P_0402_25V7K  [C_0402]  23.3 123.27 270 bottom
CE10  0.1U_0201_10V6K  [C_0201]  23.62 106.62 270 bottom
CE11  12P_0402_50V8J  [C_0402]  32.51 110.49 90 bottom
CE12  10P_0402_50V8J  [C_0402]  32.51 109.6 270 bottom
CE13  2200P_0402_50V7K  [C_0402]  20.7 106.62 0 bottom
CE14  1U_0402_6.3V6K  [C_0402]  32.64 114.87 0 bottom
CE15  0.1U_0201_10V6K  [C_0201]  32.74 121.26 90 bottom
CE18  0.1U_0201_10V6K  [C_0201]  32.45 107.76 0 bottom
CE19  2200P_0201_16V7K  [C_0201]  18.96 105.4 0 bottom
CE21  2.2U_0402_6.3V6K  [C_0402]  36.96 106.75 0 bottom
CE24  1U_0402_6.3V4Z  [C_0402]  26.1 120.64 90 bottom
CE25  0.1U_0201_10V6K  [C_0201]  18.03 119.62 0 bottom
CE26  100P_0402_50V8J  [C_0402]  144.02 110.97 180 bottom
CE27  2200P_0402_50V7K  [C_0402]  33.41 116.91 180 bottom
CE28  2200P_0402_50V7K  [C_0402]  33.41 117.79 180 bottom
CE29  2200P_0402_50V7K  [C_0402]  33.41 118.68 180 bottom
CE30  0.1U_0402_10V7K  [C_0402]  30.26 121.55 270 bottom
CE46  10U_0603_6.3V6M  [C_0603]  16.89 114.62 0 bottom
CE47  22U_0603_6.3V6M  [C_0603]  26.66 105.86 180 bottom
CE48  0.1U_0201_10V6K  [C_0201]  26.35 106.75 180 bottom
CE49  0.1U_0201_10V6K  [C_0201]  24.5 106.68 270 bottom
CE54  0.1U_0201_10V6K  [C_0201]  16.89 110.94 0 bottom
CE55  0.1U_0201_10V6K  [C_0201]  18.67 110.94 180 bottom
CE57  10P_0402_50V8J  [C_0402]  27.56 106.57 270 bottom
CE64  1U_0402_6.3V6K  [C_0402]  23.88 104.71 0 bottom
CE65  33P_0402_50V8J  [C_0402]  24.19 102.92 90 bottom
CE78  4700P_0402_25V7K  [C_0402]  28.32 124.4 180 bottom
CE86  0.1U_0402_25V6  [C_0402]  18.97 122.43 0 bottom
CE87  4700P_0402_25V7K  [C_0402]  26.85 103.82 270 bottom
CE88  0.1U_0201_10V6K  [C_0201]  18.67 117.29 180 bottom
CLIP1  EMI_SPRING  [EMIST_SU-27AS_1P]  19.76 165.17 65 top
CLIP2  EMI_SPRING  [EMIST_SU-27AS_1P]  42.66 95.83 90 top
CLIP3  EMI_SPRING  [EMIST_SUL-12A2M_1P]  42.7 79.15 90 top
CLIP4  EMI_SPRING  [EMIST_SUL-12A2M_1P]  42.7 45.15 90 top
CLIP5  EMI_SPRING  [EMIST_SUL-12A2M_1P]  57.25 89.65 0 top
CLIP6  EMI_SPRING  [EMIST_SUL-12A2M_1P]  67.9 79.15 90 top
CLIP7  EMI_SPRING  [EMIST_SUL-12A2M_1P]  11.3 116.15 90 top
CLIP8  EMI_SPRING  [EMIST_SUL-12A2M_1P]  20.6 105.95 0 top
CLIP9  EMI_SPRING  [EMIST_SUL-12A2M_1P]  30.5 105.95 0 top
CLIP10  EMI_SPRING  [EMIST_SUL-12A2M_1P]  36 116.15 90 top
CLIP11  EMI_SPRING  [EMIST_SUL-12A2M_1P]  16.28 55.6 90 top
CLIP12  EMI_SPRING  [EMIST_SUL-12A2M_1P]  41.17 55.6 90 top
CLIP13  EMI_SPRING  [EMIST_SU-27AS_1P]  60.93 92.51 270 top
CLIP14  EMI_SPRING  [EMIST_SUL-12A2M_1P]  67.9 45.15 90 top
CLRP1  10K_0201_5%  [R_0201]  65.56 104.08 270 top
CMOS1  SHORT PADS~D  [SHORTPADS]  62.99 104.71 90 top
CR1  10U_0402_6.3V6M  [C_0402]  73.28 82.54 90 bottom
CR2  0.1U_0402_10V7K  [C_0402]  72.39 83.45 270 bottom
CR3  4.7U_0402_6.3V6M  [C_0402]  70.69 65.47 180 top
CR4  0.1U_0402_10V7K  [C_0402]  70.69 64.58 180 top
CR5  4.7U_0402_6.3V6M  [C_0402]  70.28 38.17 0 bottom
CR6  0.1U_0402_10V7K  [C_0402]  71.2 37.28 180 bottom
CR7  10U_0402_6.3V6M  [C_0402]  69.34 37.2 90 bottom
CR8  0.1U_0402_10V7K  [C_0402]  68.45 38.11 270 bottom
CR9  0.1U_0402_10V7K  [C_0402]  66.6 38.17 0 bottom
CR10  2.2P_0402_50V8C~D  [C_0402]  74.6 38.35 0 bottom
CR11  2.2P_0402_50V8C~D  [C_0402]  74.6 37.46 0 bottom
CR12  0.1U_0402_10V7K  [C_0402]  63.87 36.01 0 bottom
CR13  2.2P_0402_50V8C~D  [C_0402]  74.6 36.57 0 bottom
CR14  0.1U_0402_10V7K  [C_0402]  63.87 35.12 0 bottom
CR15  1U_0402_6.3V6K  [C_0402]  73.48 35.68 180 bottom
CR16  2.2P_0402_50V8C~D  [C_0402]  74.38 34.79 0 bottom
CR17  2.2P_0402_50V8C~D  [C_0402]  74.35 33.9 0 bottom
CR18  2.2P_0402_50V8C~D  [C_0402]  74.38 33.01 0 bottom
CR19  1U_0402_6.3V6K  [C_0402]  73.48 30.55 180 bottom
CR20  0.1U_0402_10V7K  [C_0402]  71.07 29.28 180 bottom
CR21  4.7U_0402_6.3V6M  [C_0402]  70.15 28.39 0 bottom
CR22  0.1U_0402_10V7K  [C_0402]  63.6 31.33 0 bottom
CR23  0.1U_0402_10V7K  [C_0402]  63.6 32.22 0 bottom
CS1  0.1U_0201_10V6K  [C_0201]  118.82 156.02 0 bottom
CS2  0.1U_0201_10V6K  [C_0201]  118.82 156.66 0 bottom
CS3  0.1U_0201_10V6K  [C_0201]  5.65 141.9 270 bottom
CS4  10U_0402_6.3V6M  [C_0402]  9.14 146.93 90 bottom
CS5  0.1U_0201_10V6K  [C_0201]  9.91 146.84 90 bottom
CS6  10U_0402_6.3V6M  [C_0402]  4.06 114.06 270 top
CS7  0.1U_0201_10V6K  [C_0201]  4.95 119.66 90 top
CS8  0.22U_0402_10V6K  [C_0402]  2.17 119.85 0 top
CS9  0.1U_0201_10V6K  [C_0201]  4.83 113.83 270 top
CS10  1U_0201_6.3V6K  [C_0201]  125.92 173.85 0 top
CT1  10U_0603_25V6M  [C_0603]  9.15 40.57 90 top
CT2  0.1U_0402_25V6  [C_0402]  3.24 33.85 180 top
CT3  0.1U_0402_25V6  [C_0402]  9.13 31.71 270 top
CT4  10U_0603_25V6M  [C_0603]  9.14 25.59 90 top
CT5  0.1U_0201_10V6K  [C_0201]  25.49 69.9 90 bottom
CT6  0.22U_0402_16V7K  [C_0402]  35.8 68.95 90 bottom
CT7  220P_0201_25V7K  [C_0201]  39.2 70.69 180 bottom
CT8  220P_0201_25V7K  [C_0201]  38.02 70.74 180 bottom
CT9  10U_0402_6.3V6M  [C_0402]  31.19 65.47 180 bottom
CT10  2.2U_0402_6.3V6M  [C_0402]  31.25 67.57 180 bottom
CT11  1U_0402_25V6K  [C_0402]  39.66 67.95 0 bottom
CT12  2.2U_0402_6.3V6M  [C_0402]  43.24 66.79 90 bottom
CT13  1U_0201_6.3V6K  [C_0201]  31.22 66.82 180 bottom
CT14  1U_0201_6.3V6K  [C_0201]  31.22 66.23 180 bottom
CT15  2.2U_0402_6.3V6M  [C_0402]  31.19 62.8 180 bottom
CT16  4.7U_0402_6.3V6M  [C_0402]  40.44 62.8 0 bottom
CT17  4.7U_0402_6.3V6M  [C_0402]  40.44 61.79 0 bottom
CT18  10U_0402_6.3V6M  [C_0402]  31.06 61.66 180 bottom
CT19  1U_0402_25V6K  [C_0402]  38.86 60.59 270 bottom
CT20  2.2U_0402_6.3V6M  [C_0402]  54.43 25.27 180 bottom
CT21  4.7U_0402_6.3V6M  [C_0402]  59.44 22.47 90 bottom
CT22  4.7U_0402_6.3V6M  [C_0402]  58.42 22.47 90 bottom
CT23  1U_0402_25V6K  [C_0402]  53.34 22.47 90 bottom
CT24  1U_0402_25V6K  [C_0402]  60.63 21.01 0 bottom
CT25  220P_0201_25V7K  [C_0201]  51.69 20.92 0 bottom
CT26  220P_0201_25V7K  [C_0201]  51.69 19.75 0 bottom
CT27  0.22U_0402_16V7K  [C_0402]  51.99 18.99 180 bottom
CT28  1U_0201_6.3V6K  [C_0201]  54.23 13.95 270 bottom
CT29  10U_0402_6.3V6M  [C_0402]  60.2 13.86 270 bottom
CT30  2.2U_0402_6.3V6M  [C_0402]  57.09 13.86 270 bottom
CT31  10U_0402_6.3V6M  [C_0402]  55.12 13.86 270 bottom
CT32  2.2U_0402_6.3V6M  [C_0402]  52.58 13.86 270 bottom
CT33  1U_0201_6.3V6K  [C_0201]  54.23 12.09 90 bottom
CT34  0.1U_0201_10V6K  [C_0201]  26.62 67.86 0 bottom
CT35  0.1U_0201_10V6K  [C_0201]  26.63 68.65 0 bottom
CT36  0.1U_0201_10V6K  [C_0201]  49.16 11.27 0 bottom
CT37  0.1U_0201_10V6K  [C_0201]  49.17 11.84 0 bottom
CV1  0.22U_0402_10V6K  [C_0402]  21.34 111.62 90 top
CV2  0.22U_0402_10V6K  [C_0402]  22.23 111.62 90 top
CV9  .1U_0402_16V7K  [C_0402]  28.7 56.4 270 bottom
CV10  .1U_0402_16V7K  [C_0402]  27.81 56.4 270 bottom
CV17  10U_0402_6.3V6M  [C_0402]  24.51 50.15 90 bottom
CV18  10U_0402_6.3V6M  [C_0402]  25.4 50.15 90 bottom
CV19  0.1U_0201_10V6K  [C_0201]  22.69 45.53 0 bottom
CV20  0.1U_0201_10V6K  [C_0201]  24.57 45.12 270 bottom
CV21  0.1U_0201_10V6K  [C_0201]  23.94 45.12 270 bottom
CV22  0.1U_0201_10V6K  [C_0201]  21.97 45.44 270 bottom
CV23  0.1U_0201_10V6K  [C_0201]  21.34 45.44 270 bottom
CV24  0.1U_0201_10V6K  [C_0201]  26.45 42.86 180 bottom
CV25  0.1U_0201_10V6K  [C_0201]  26.45 42.23 180 bottom
CV26  0.1U_0201_10V6K  [C_0201]  26.45 41.59 180 bottom
CV27  0.1U_0201_10V6K  [C_0201]  17.78 41.05 90 bottom
CV28  0.1U_0201_10V6K  [C_0201]  26.45 40.96 180 bottom
CV29  0.1U_0201_10V6K  [C_0201]  17.07 41.05 90 bottom
CV30  0.1U_0201_10V6K  [C_0201]  26.45 40.32 180 bottom
CV31  0.1U_0201_10V6K  [C_0201]  18.33 39.94 180 bottom
CV32  0.1U_0201_10V6K  [C_0201]  26.45 39.69 180 bottom
CV33  0.1U_0201_10V6K  [C_0201]  18.33 39.31 180 bottom
CV34  0.1U_0201_10V6K  [C_0201]  26.45 38.42 180 bottom
CV35  0.1U_0201_10V6K  [C_0201]  26.45 37.78 180 bottom
CV36  0.1U_0201_10V6K  [C_0201]  25.87 39.05 0 bottom
CV39  0.1U_0201_10V6K  [C_0201]  18.8 36.43 270 bottom
CV40  0.1U_0201_10V6K  [C_0201]  24.26 31.09 270 bottom
CV41  0.1U_0201_10V6K  [C_0201]  23.62 31.09 270 bottom
CV42  0.1U_0201_10V6K  [C_0201]  22.86 30.51 90 bottom
CV43  0.1U_0201_10V6K  [C_0201]  22.1 31.09 270 bottom
CV44  0.1U_0201_10V6K  [C_0201]  21.46 31.09 270 bottom
CV45  0.1U_0201_10V6K  [C_0201]  26.58 28.51 180 bottom
CV46  0.1U_0201_10V6K  [C_0201]  18.45 27.24 180 bottom
CV47  0.1U_0201_10V6K  [C_0201]  26.58 27.88 180 bottom
CV48  0.1U_0201_10V6K  [C_0201]  18.45 26.61 180 bottom
CV49  0.1U_0201_10V6K  [C_0201]  26.58 27.24 180 bottom
CV50  0.1U_0201_10V6K  [C_0201]  26.58 26.61 180 bottom
CV51  0.1U_0201_10V6K  [C_0201]  26.58 25.97 180 bottom
CV52  0.1U_0201_10V6K  [C_0201]  26.58 25.34 180 bottom
CV53  0.1U_0201_10V6K  [C_0201]  26.58 24.07 180 bottom
CV54  0.1U_0201_10V6K  [C_0201]  18.45 25.85 180 bottom
CV55  0.1U_0201_10V6K  [C_0201]  26.58 23.43 180 bottom
CV56  0.1U_0201_10V6K  [C_0201]  18.45 25.21 180 bottom
CV57  0.1U_0201_10V6K  [C_0201]  27.18 24.7 0 bottom
CV58  0.1U_0201_10V6K  [C_0201]  23.24 20.47 90 bottom
CV59  0.1U_0201_10V6K  [C_0201]  22.61 20.47 90 bottom
CV60  0.1U_0201_10V6K  [C_0201]  19.01 21.4 0 bottom
CV61  2.2U_0402_6.3V6M  [C_0402]  17.78 44.95 90 bottom
CV62  2.2U_0402_6.3V6M  [C_0402]  18.8 32.25 90 bottom
CV63  0.1U_0201_10V6K  [C_0201]  22.48 34.79 90 bottom
CV64  0.1U_0201_10V6K  [C_0201]  21.84 34.79 90 bottom
CZ1  0.1U_0402_10V7K  [C_0402]  67.01 137.99 180 top
CZ2  0.1U_0402_10V7K  [C_0402]  69.62 105.55 180 top
CZ3  1U_0402_6.3V6K  [C_0402]  72.58 99.63 180 top
CZ4  0.1U_0402_10V7K  [C_0402]  59.39 138.11 180 bottom
CZ5  0.1U_0402_10V7K  [C_0402]  52.32 138.32 270 bottom
CZ6  1U_0402_6.3V6K  [C_0402]  62.41 135.57 0 bottom
CZ7  1U_0402_6.3V6K  [C_0402]  54.28 132.53 0 bottom
CZ8  1U_0402_6.3V6K  [C_0402]  50.88 131.76 180 bottom
CZ9  0.1U_0402_10V7K  [C_0402]  55.07 130.14 180 bottom
CZ10  0.1U_0402_10V7K  [C_0402]  58.55 127.14 270 bottom
D1  ESD8011MUT5G X3DFN2  [ESD101-B1-02ELS_TSSLP-2-4-2]  119 173.74 90 top
D2  ESD8011MUT5G X3DFN2  [ESD101-B1-02ELS_TSSLP-2-4-2]  120.14 171.71 90 top
D3  ESD8011MUT5G X3DFN2  [ESD101-B1-02ELS_TSSLP-2-4-2]  119 173.1 270 top
D4  ESD8011MUT5G X3DFN2  [ESD101-B1-02ELS_TSSLP-2-4-2]  120.14 171.07 270 top
D5  ESD8011MUT5G X3DFN2  [ESD101-B1-02ELS_TSSLP-2-4-2]  125.6 169.67 270 top
D6  ESD8011MUT5G X3DFN2  [ESD101-B1-02ELS_TSSLP-2-4-2]  120.14 169.67 90 top
D7  ESD8011MUT5G X3DFN2  [ESD101-B1-02ELS_TSSLP-2-4-2]  120.14 169.04 270 top
D8  ESD8011MUT5G X3DFN2  [ESD101-B1-02ELS_TSSLP-2-4-2]  120.14 167.64 90 top
D9  ESD8011MUT5G X3DFN2  [ESD101-B1-02ELS_TSSLP-2-4-2]  120.14 167.01 270 top
D10  ESD8011MUT5G X3DFN2  [ESD101-B1-02ELS_TSSLP-2-4-2]  119.89 156.21 90 top
D11  ESD8011MUT5G X3DFN2  [ESD101-B1-02ELS_TSSLP-2-4-2]  119.89 155.58 270 top
D12  ESD8011MUT5G X3DFN2  [ESD101-B1-02ELS_TSSLP-2-4-2]  119.89 158.24 90 top
D13  ESD8011MUT5G X3DFN2  [ESD101-B1-02ELS_TSSLP-2-4-2]  119.89 157.61 270 top
D14  ESD8011MUT5G X3DFN2  [ESD101-B1-02ELS_TSSLP-2-4-2]  119.89 162.31 90 top
D15  ESD8011MUT5G X3DFN2  [ESD101-B1-02ELS_TSSLP-2-4-2]  119.89 161.67 270 top
D16  ESD8011MUT5G X3DFN2  [ESD101-B1-02ELS_TSSLP-2-4-2]  119.89 160.28 90 top
D17  ESD8011MUT5G X3DFN2  [ESD101-B1-02ELS_TSSLP-2-4-2]  119.89 159.64 270 top
D18  ESD8011MUT5G X3DFN2  [ESD101-B1-02ELS_TSSLP-2-4-2]  119.89 164.34 90 top
D19  ESD8011MUT5G X3DFN2  [ESD101-B1-02ELS_TSSLP-2-4-2]  119.89 163.7 270 top
D20  -  [ESD207-B1-02EL_TSLP-2-19-2]  5.64 154.37 0 top
D21  -  [ESD207-B1-02EL_TSLP-2-19-2]  5.77 141.04 0 top
D22  RB751S40T1G_SOD523-2  [RB520SM-30T2R_EMD2-2]  153.42 134.31 300 top
D39  -  [BAT54CW-7-F_SOT323-3]  66.17 92.75 0 bottom
D40  -  [BAT54CW-7-F_SOT323-3]  70.31 92.56 0 bottom
D48  ESD8011MUT5G X3DFN2  [ESD101-B1-02ELS_TSSLP-2-4-2]  8.57 44.2 90 top
D49  ESD8011MUT5G X3DFN2  [ESD101-B1-02ELS_TSSLP-2-4-2]  8.57 43.56 270 top
D50  ESD8011MUT5G X3DFN2  [ESD101-B1-02ELS_TSSLP-2-4-2]  9.4 44.9 270 top
D51  ESD8011MUT5G X3DFN2  [ESD101-B1-02ELS_TSSLP-2-4-2]  14.1 36.2 90 bottom
D52  ESD8011MUT5G X3DFN2  [ESD101-B1-02ELS_TSSLP-2-4-2]  9.08 37.84 180 top
